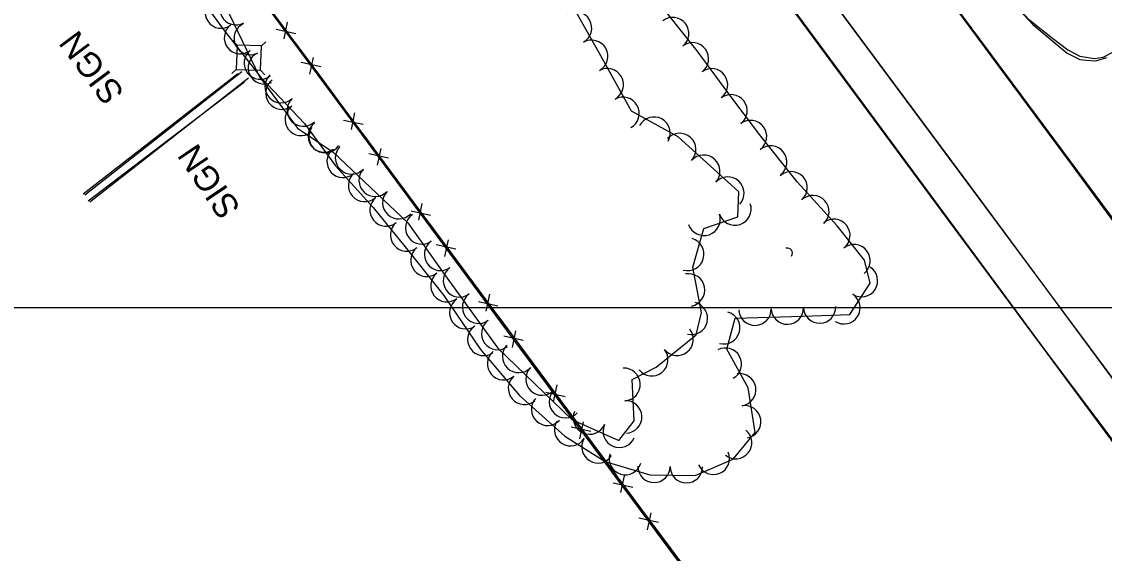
# Model space of a CAD drawing. Extents: x 353423 to 364002, y 127000 to 201942.
# Drawn here: x 360516.5 to 360782.5, y 130439.6 to 130570.2 of the extents above; entities that cross this region are included whole.
import ezdxf

# ---------------------------------------------------------------- set-up
doc = ezdxf.new("R2010")
doc.units = 0
for name, color, linetype in [('E_DTM_SlopeBottom', 7, 'Continuous'), ('E_DTM_SlopeTop', 7, 'Continuous'), ('E_FEN_Generic', 7, 'Continuous'), ('E_LAND_BrushLine', 7, 'Continuous'), ('E_LAND_TreeLine', 7, 'Continuous'), ('E_SGN', 7, 'Continuous')]:
    doc.layers.add(name, color=color, linetype=linetype)

msp = doc.modelspace()

# ---------------------------------------------------------------- linework, layer by layer
at = {"layer": 'E_DTM_SlopeBottom'}
for p, q in [((360581.76, 130570.08), (360580.88, 130565.96)), ((360579.06, 130568.29), (360583.86, 130567.24)), ((360590.03, 130559.06), (360585.21, 130560.11)), ((360587.33, 130557.26), (360588.2, 130561.4)), ((360595.62, 130546), (360600.42, 130544.95)), ((360598.31, 130547.79), (360597.44, 130543.67)), ((360603.91, 130534.88), (360604.8, 130539.01)), ((360606.62, 130536.67), (360601.8, 130537.73)), ((360614.87, 130525.51), (360613.99, 130521.39)), ((360612.18, 130523.72), (360616.98, 130522.67)), ((360620.49, 130512.49), (360621.37, 130516.62)), ((360623.19, 130514.28), (360618.38, 130515.34)), ((360628.73, 130501.43), (360633.53, 130500.39)), ((360631.42, 130503.22), (360630.55, 130499.1)), ((360639.77, 130491.89), (360634.95, 130492.95)), ((360637.07, 130490.1), (360637.95, 130494.23)), ((360647.98, 130480.94), (360647.1, 130476.82)), ((360645.29, 130479.15), (360650.09, 130478.1)), ((360653.68, 130467.73), (360654.56, 130471.86)), ((360656.38, 130469.52), (360651.56, 130470.57)), ((360664.54, 130458.65), (360663.66, 130454.53)), ((360661.84, 130456.86), (360666.64, 130455.82)), ((360672.99, 130447.16), (360668.18, 130448.21)), ((360670.29, 130445.36), (360671.17, 130449.5))]:
    msp.add_line(p, q, dxfattribs=at)
for points in [[(361092.35, 129877.19), (361044.92, 129941.89), (360997.56, 130006.24), (360962.5, 130053.48), (360925.13, 130103.47), (360878.83, 130166.15), (360830.3, 130231.49), (360791.79, 130283.41), (360741.39, 130351.57), (360693.7, 130416.36), (360638.93, 130490.09), (360591.48, 130554.19), (360546.89, 130614.15), (360499.36, 130678.34), (360464.05, 130726.01), (360438.2, 130761.06), (360411.43, 130797.18), (360381.21, 130837.79)], [(360407.27, 130804.74), (360439.73, 130759.75), (360490.26, 130690.73), (360670.73, 130447.81), (360721.87, 130378.76), (360826.04, 130237.28), (360883.23, 130160.42), (360930.64, 130096.44), (361000.73, 130001.84), (361082.18, 129891.3), (361106.51, 129856.97), (361154.89, 129791.52), (361182.92, 129753.46), (361188.88, 129640.57), (361196.9, 129546.21), (361209.22, 129452.29), (361221.13, 129367.62), (361233.6, 129282.65)], [(360585.4, 130562.37), (360578.64, 130571.46)], [(360583.68, 130564.98), (360590.4, 130555.93)], [(360595.26, 130549.09), (360591.48, 130554.19), (360589.33, 130557.09)], [(360590.4, 130555.93), (360596.32, 130547.96)], [(360601.99, 130539.99), (360595.26, 130549.09)], [(360600.23, 130542.7), (360606.96, 130533.64)], [(360611.83, 130526.7), (360605.91, 130534.7)], [(360606.96, 130533.64), (360612.88, 130525.68)], [(360618.57, 130517.6), (360611.83, 130526.7)], [(360616.79, 130520.41), (360623.52, 130511.36)], [(360628.41, 130504.31), (360622.48, 130512.31)], [(360623.52, 130511.36), (360629.43, 130503.39)], [(360635.15, 130495.21), (360628.41, 130504.31)], [(360633.35, 130498.13), (360640.07, 130489.07)], [(360645, 130481.93), (360639.06, 130489.92)], [(360640.07, 130489.07), (360645.99, 130481.11)], [(360651.75, 130472.84), (360645, 130481.93)], [(360649.9, 130475.85), (360656.63, 130466.79)], [(360661.61, 130459.56), (360655.67, 130467.55)], [(360656.63, 130466.79), (360662.55, 130458.82)], [(360668.36, 130450.47), (360661.61, 130459.56)], [(360666.46, 130453.56), (360670.73, 130447.81), (360673.18, 130444.5)], [(360678.23, 130437.2), (360672.29, 130445.19)], [(360673.18, 130444.5), (360679.09, 130436.53)]]:
    msp.add_lwpolyline(points, dxfattribs=at)
msp.add_ellipse((360703.93, 130512.82), major_axis=(1.76, 1.24), ratio=0.686067, start_param=5.356084, end_param=7.210314, dxfattribs=at)
at = {"layer": 'E_DTM_SlopeTop'}
for points in [[(360812.38, 130484.47), (360679.44, 130663.54), (360601.08, 130770.21), (360543.32, 130848.21), (360486.67, 130924.56), (360443.57, 130982.64), (360405.94, 131033.09), (360347.68, 131112.32), (360339.61, 131123.22)], [(361334.82, 129736.64), (361276.43, 129817.07), (361218.41, 129895.06), (361173.92, 129955.59), (361116.6, 130033.88), (361057.88, 130112.91), (361005.23, 130183.79), (360919.7, 130299.92), (360859.57, 130381.04), (360802.73, 130458.17), (360712.34, 130579.92), (360650.2, 130664.74), (360583.26, 130754.37), (360522.68, 130834.6), (360443.16, 130936.49), (360381.32, 131015.53), (360355.42, 131048.77)], [(360359.06, 131031.63), (360412.77, 130962.23), (360456.51, 130906.46), (360514.58, 130829.11), (360575.61, 130749.78), (360615.66, 130696.58), (360651.09, 130648.19), (360678.79, 130610.26), (360711.14, 130566.37), (360768.38, 130488.8), (360811.24, 130431.97), (360853.39, 130374.54), (360875.99, 130343.44), (360911.98, 130295.27), (360943.46, 130251.36), (360971.6, 130213.46), (361000.8, 130174.05), (361030.19, 130135.22), (361061.21, 130091.97), (361110.81, 130026.56), (361166.93, 129950.76), (361239.61, 129851.93), (361335.43, 129723.6)], [(360539.14, 130812.53), (360565.51, 130777.84), (360593.87, 130739.91), (360625.54, 130697.03), (360652.65, 130660.22), (360685.53, 130616.09), (360714.56, 130576.84), (360749.27, 130530.18), (360775.57, 130494.65), (360810.61, 130447.18), (360838.14, 130409.72), (360879.43, 130354.21), (360906.49, 130317.48), (360944.28, 130266.52), (360972.83, 130227.69), (361006.65, 130182.14), (361037.04, 130141.05), (361070.51, 130095.92), (361098.26, 130058.32), (361129.55, 130016.03), (361157.08, 129978.62), (361188.2, 129936.52), (361215.22, 129899.89), (361236.43, 129871.54)], [(360529.26, 130810.15), (360554.27, 130777.79), (360574.26, 130750.78), (360595.98, 130721.64), (360615.36, 130695.63), (360638.79, 130663.72), (360656.49, 130640.14), (360678.56, 130609.95), (360700.65, 130580.24), (360724.42, 130548.06), (360743.96, 130521.7), (360768.43, 130488.72), (360792.03, 130456.94), (360810.78, 130431.34)], [(360570.32, 130810.78), (360600.22, 130770.91), (360638.59, 130718.65), (360671.71, 130673.89), (360707.05, 130626.12), (360742.48, 130578.27), (360774.17, 130535.49), (360800.97, 130499.08), (360825.44, 130466.23), (360849.91, 130433.42), (360876.06, 130397.89), (360904.66, 130359.17), (360936.36, 130316.65), (360963.75, 130279.7), (360997.86, 130233.57), (361031.14, 130188.46), (361063.99, 130144.35), (361101.47, 130093.76), (361133.47, 130050.11), (361168.56, 130002.53), (361203.91, 129954.89), (361239.46, 129906.99), (361266.3, 129870.87)], [(360575.18, 130810.12), (360596.24, 130781.82), (360623.79, 130744.57), (360648.33, 130711.2), (360671.72, 130679.59), (360689.22, 130656.1), (360698.8, 130644.93), (360715.58, 130625.81), (360728.01, 130611.1), (360747.76, 130588.17), (360764.98, 130569.46), (360773.42, 130562.42), (360776.51, 130560.85), (360778.18, 130560.7), (360780.45, 130560.58), (360783.15, 130561.35)], [(360700.18, 130641.03), (360737.14, 130600.93), (360763.85, 130570.82), (360769.77, 130566.08), (360773.6, 130563.21), (360776.55, 130561.69), (360780.15, 130561.12), (360782.23, 130561.45), (360784.62, 130562.66), (360787.38, 130564.54), (360788.44, 130567), (360788.91, 130570.68), (360788.59, 130574), (360775.19, 130612.07)]]:
    msp.add_lwpolyline(points, dxfattribs=at)
at = {"layer": 'E_FEN_Generic'}
for points in [[(360556.81, 130580.9), (360565.99, 130568.29), (360575.34, 130556.35), (360585.96, 130545.15), (360593.65, 130534.76), (360602.83, 130524.53), (360611.75, 130513.66), (360620.21, 130502.95), (360629.21, 130489.63), (360638.79, 130478.35), (360649.97, 130468.35), (360659.85, 130462.18), (360670.87, 130458.87), (360682.01, 130458.74), (360691.31, 130462.68), (360696.72, 130469.3), (360694.99, 130480.21), (360689.79, 130489.73), (360691.79, 130497.31), (360708.46, 130497.85), (360720, 130498.28), (360724.97, 130505.97), (360723.6, 130511.56), (360716.86, 130520.05), (360707.06, 130530.84), (360697.82, 130542.48), (360690.25, 130552.45), (360682.48, 130563), (360671.92, 130576.34)], [(360567.45, 130572.09), (360574.9, 130556.6), (360584.26, 130543.98), (360593.08, 130538.08), (360611.39, 130520.75), (360620.41, 130508.05), (360633.53, 130489.96), (360651.66, 130472.47), (360663.26, 130467.33), (360667.04, 130472.1), (360666.54, 130482.27), (360672.41, 130485.33), (360682.23, 130493.24), (360683.54, 130498.7), (360681.44, 130509.86), (360684.1, 130519.4), (360692.45, 130522.2), (360692.75, 130528.39), (360677.84, 130541.9), (360666.36, 130548.15), (360658.44, 130562.53), (360649.12, 130578.93)]]:
    msp.add_lwpolyline(points, dxfattribs=at)
for centre, radius, start, end in [((360565.5, 130572.5), 3.97, 126.0407, 306.0254), ((360569.13, 130573.37), 4, 119.4475, 299.4322), ((360652.59, 130568.6), 4, 299.5858, 119.5705), ((360676.48, 130567.24), 3.97, 308.3867, 128.3714), ((360570.24, 130566.23), 3.97, 128.0755, 308.0602), ((360572.68, 130566.05), 4, 115.7139, 295.6986), ((360656.53, 130561.64), 4, 299.5858, 119.5705), ((360681.34, 130561.05), 3.97, 306.3774, 126.3621), ((360575.13, 130559.98), 3.97, 128.0755, 308.0602), ((360576.15, 130558.84), 4, 115.7139, 295.6986), ((360580.25, 130554.19), 3.97, 133.4935, 313.4782), ((360660.38, 130554.66), 4, 298.8563, 118.841), ((360686.04, 130554.66), 3.97, 306.3774, 126.3621), ((360580.47, 130552.61), 4, 126.5574, 306.542), ((360585.71, 130548.43), 3.97, 133.4935, 313.4782), ((360664.24, 130547.65), 4, 298.8563, 118.841), ((360690.81, 130548.28), 3.97, 307.2107, 127.1954), ((360585.23, 130546.18), 4, 126.5574, 306.542), ((360671.87, 130542.76), 4, 331.4304, 151.415), ((360695.61, 130541.96), 3.97, 307.2107, 127.1954), ((360590.83, 130542.06), 3.97, 126.513, 306.4977), ((360591.08, 130541.94), 4, 146.2359, 326.2206), ((360678.17, 130538.77), 4, 317.8453, 137.8299), ((360595.46, 130535.85), 3.97, 131.9208, 311.9055), ((360597.57, 130536.72), 4, 136.589, 316.5737), ((360700.55, 130535.7), 3.97, 308.4495, 128.4341), ((360684.09, 130533.4), 4, 317.8453, 137.8299), ((360600.76, 130529.95), 3.97, 131.9208, 311.9055), ((360603.38, 130531.22), 4, 136.589, 316.5737), ((360705.58, 130529.38), 3.97, 312.2692, 132.2539), ((360690.02, 130528.03), 4, 317.8453, 137.8299), ((360609.19, 130525.72), 4, 136.589, 316.5737), ((360710.92, 130523.51), 3.97, 312.2692, 132.2539), ((360606.04, 130523.9), 3.97, 129.3478, 309.3325), ((360691.76, 130524.18), 4, 198.5515, 18.5361), ((360614.83, 130519.53), 4, 125.3712, 305.3559), ((360684.18, 130521.64), 4, 198.5515, 18.5361), ((360611.07, 130517.76), 3.97, 129.3478, 309.3325), ((360716.09, 130517.68), 3.97, 308.4123, 128.397), ((360680.15, 130513.02), 4, 254.4416, 74.4263), ((360616.06, 130511.55), 3.97, 128.3436, 308.3283), ((360619.46, 130513.01), 4, 125.3712, 305.3559), ((360721.02, 130511.46), 3.97, 308.4123, 128.397), ((360624.1, 130506.52), 4, 125.967, 305.9517), ((360722.87, 130506.55), 3.97, 237.121, 57.1056), ((360620.99, 130505.32), 3.97, 128.3436, 308.3283), ((360680.36, 130504.26), 4, 280.6652, 100.6499), ((360625.6, 130498.68), 3.97, 124.0455, 304.0302), ((360628.8, 130500.05), 4, 125.967, 305.9517), ((360681.05, 130497.3), 4, 256.5134, 76.4981), ((360718.56, 130499.88), 3.97, 237.121, 57.1056), ((360689.03, 130494.98), 3.97, 255.1662, 75.1509), ((360696.7, 130499.54), 3.97, 181.8774, 1.8621), ((360704.63, 130499.8), 3.97, 181.8774, 1.8621), ((360712.56, 130500.08), 3.97, 182.1409, 2.1256), ((360630.05, 130492.11), 3.97, 124.0455, 304.0302), ((360633.5, 130493.58), 4, 125.967, 305.9517), ((360677.55, 130492.15), 4, 218.8508, 38.8355), ((360638.62, 130487.96), 4, 136.0373, 316.0219), ((360689.43, 130486.06), 3.97, 298.6582, 118.6428), ((360634.91, 130486.13), 3.97, 130.3591, 310.3437), ((360671.32, 130487.14), 4, 218.8508, 38.8355), ((360644.38, 130482.41), 4, 136.0373, 316.0219), ((360664.5, 130481.07), 4, 272.8394, 92.8241), ((360640.04, 130480.09), 3.97, 130.3591, 310.3437), ((360692.96, 130479.75), 3.97, 279.0221, 99.0068), ((360650.13, 130476.85), 4, 136.0373, 316.0219), ((360645.71, 130474.95), 3.97, 138.1957, 318.1804), ((360664.9, 130473.08), 4, 272.8394, 92.8241), ((360656.04, 130472.82), 4, 156.1219, 336.1066), ((360694.2, 130471.91), 3.97, 279.0221, 99.0068), ((360651.38, 130469.92), 3.97, 148.0289, 328.0135), ((360663.35, 130469.58), 4, 156.1219, 336.1066), ((360691.97, 130466.77), 3.97, 230.7861, 50.7708), ((360658.11, 130465.72), 3.97, 148.0289, 328.0135), ((360664.84, 130462.85), 3.97, 163.2631, 343.2478), ((360686.49, 130462.9), 3.97, 202.9277, 22.9124), ((360671.91, 130460.93), 3.97, 179.3645, 359.3492), ((360679.84, 130460.84), 3.97, 179.3645, 359.3492)]:
    msp.add_arc(centre, radius, start, end, dxfattribs=at)
at = {"layer": 'E_LAND_BrushLine'}
for p, q in [((360570.58, 130557.82), (360531.98, 130527.59)), ((360572.23, 130556.25), (360533.28, 130525.85))]:
    msp.add_line(p, q, dxfattribs=at)
for points in [[(360531.62, 130527.89), (360569.65, 130557.43)], [(360571.27, 130555.3), (360532.83, 130526.07)]]:
    msp.add_lwpolyline(points, dxfattribs=at)
at = {"layer": 'E_LAND_TreeLine'}
msp.add_line((360000, 130500), (363500, 130500), dxfattribs=at)
at = {"layer": 'E_SGN'}
for p, q in [((360569.44, 130564.42), (360568.42, 130565.52)), ((360576.53, 130565.23), (360575.43, 130564.21)), ((360569.23, 130558.42), (360568.13, 130557.4)), ((360576.24, 130557.11), (360575.22, 130558.21))]:
    msp.add_line(p, q, dxfattribs=at)
msp.add_lwpolyline([(360575.22, 130558.21), (360575.43, 130564.21), (360569.44, 130564.42), (360569.23, 130558.42)], close=True, dxfattribs=at)

# ---------------------------------------------------------------- texts
at = {"layer": 'E_LAND_BrushLine'}
for rotation, p in [(126.7563, (360541.92, 130552.74)), (123.9521, (360570.46, 130524.4))]:
    msp.add_text('SIGN', height=6, rotation=rotation, dxfattribs=at).set_placement(p)

doc.saveas('drawing.dxf')
